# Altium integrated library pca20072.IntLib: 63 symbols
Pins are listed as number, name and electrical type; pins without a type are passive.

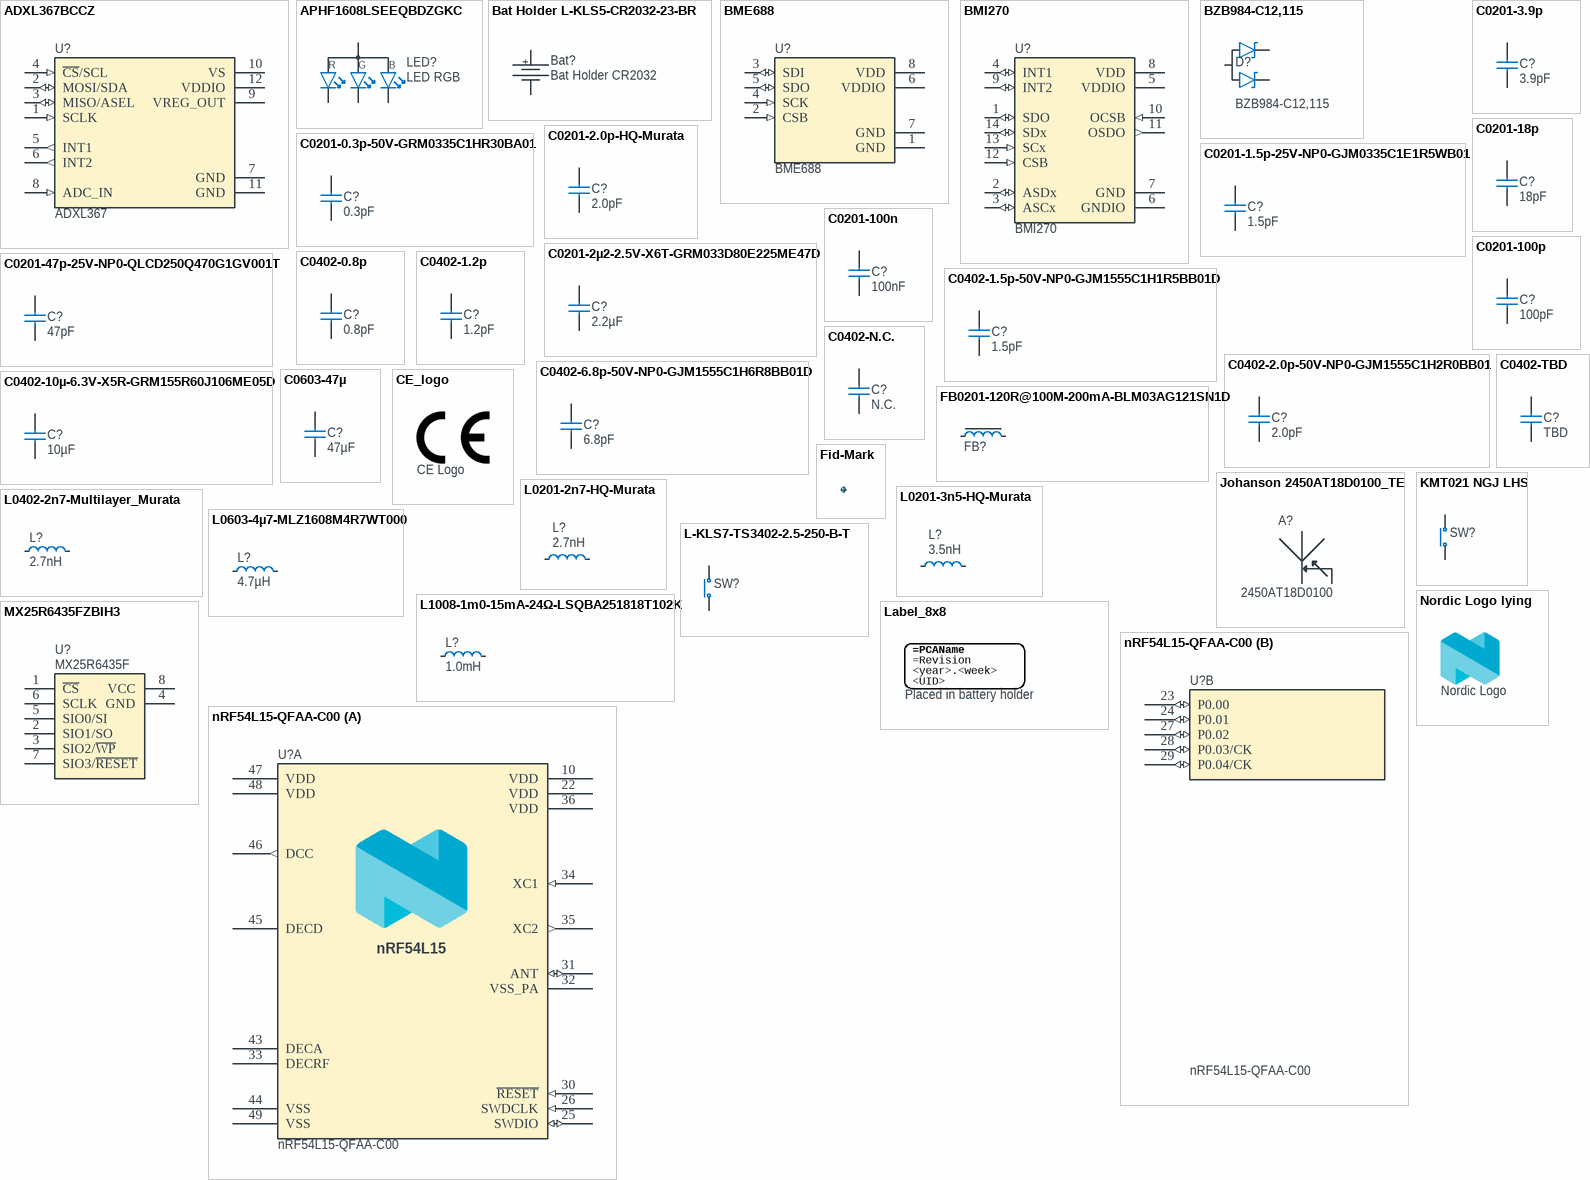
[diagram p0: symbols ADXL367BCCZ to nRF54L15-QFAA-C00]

## ADXL367BCCZ
designator U?, comment ADXL367
Micropower, 3-Axis, ±2 g/±4 g/±8 g Digital Output MEMS Accelerometer; Part Number: ADXL367BCCZ; Manufacturer: Analog Devices; Part number NEMS: 101900775; Note: N.A.; Component Status: Active; Pad Count: 12
footprint LGA50P220X230X97-12N
pins: 1 SCLK (in), 2 MOSI/SDA (io), 3 MISO/ASEL (io), 4 ~{CS}/SCL (in), 5 INT1 (out), 6 INT2 (out), 7 GND (power), 8 ADC_IN (in), 9 VREG_OUT (power), 10 VS (power), 11 GND (power), 12 VDDIO (power)

## APHF1608LSEEQBDZGKC
designator LED?, comment LED RGB
RGB LED 1.60 mm x 0.80 mm SMD; Part Number: APHF1608LSEEQBDZGKC; Manufacturer: Kingbright Company LLC; Part number IPS: 00000001254; Part number Norautron: 26470023; Part number NEMS: 101400123; Note: N.A.; Pad Count: 4; Component Status: Active
footprint LED_RGB_0603
pins: 1 C_RED, 2 C_GREEN, 3 C_BLUE, 4 A

## Bat Holder L-KLS5-CR2032-23-BR
designator Bat?, comment Bat Holder CR2032
Bat Holder CR2032 SMD; Part Number: Bat Holder L-KLS5-CR2032-23-BR; Manufacturer: KLS Electronic; Manufacturer Part Number: L-KLS5-CR2032-23-BR; Part number NEMS: 100500651; Component Status: Active; Pad Count: 2; Artikkelnr Noca: N.A.; System: Connector
footprint L-KLS5-CR2032-23-B1
pins: 1, 2

## BME688
designator U?
Low power gas, pressure, temperature & humidity sensor; Manufacturer: Bosch; Part number NEMS: 101900619; Component Status: Active; Pad Count: 8; Note: N.A.
footprint BME680
pins: 1 GND (power), 2 CSB (in), 3 SDI (io), 4 SCK (in), 5 SDO (io), 6 VDDIO (power) "1.2V - 3.6V", 7 GND (power), 8 VDD (power) "1.71V - 3.6V"

## BMI270
designator U?
6-axis, smart, low-power, inertial measurement unit; Manufacturer: Bosch; Part number NEMS: 101900620; Note: N.A.; Pad Count: 14; Component Status: Active
footprint BMI270
pins: 1 SDO (io), 2 ASDx (io), 3 ASCx (io), 4 INT1 (io), 5 VDDIO (power), 6 GNDIO (power), 7 GND (power), 8 VDD (power), 9 INT2 (io), 10 OCSB (in), 11 OSDO (out), 12 CSB (in), 13 SCx (in), 14 SDx (io)

## BZB984-C12,115
designator D?
Zener Diode Array, 1 Pair, Common Anode, 12V, 265mW, ±5%; Manufacturer: Nexperia; Part number NEMS: 101300214; Component Status: Active; Pad Count: 3; Note: N.A.
footprint SOTFL50P160X60-3L
pins: 1 K1, 2 K2, 3 CA
1 alternate drawing of the same symbol

## C0201-0.3p-50V-GRM0335C1HR30BA01
designator C?, comment 0.3pF
Capacitor, C0G, ±0.1pF, 50V; Part Number: C0201-0.3p-50V-GRM0335C1HR30BA01; Manufacturer: Murata; Manufacturer Part Number: GRM0335C1HR30BA01; Part number NEMS: 100200650; Component Status: Active; Pad Count: 2; Artikkelnr Noca: N.A.
footprint CAPC0603X03L_C
pins: 1, 2

## C0201-1.5p-25V-NP0-GJM0335C1E1R5WB01
designator C?, comment 1.5pF
Capacitor, NP0, ±0.05pF, 25V, High Q; Part Number: C0201-1.5p-25V-NP0-GJM0335C1E1R5WB01; Manufacturer: Murata; Manufacturer Part Number: GJM0335C1E1R5WB01; Part number NEMS: 100200477; Component Status: Active; Pad Count: 2; Artikkelnr Noca: N.A.
footprint CAPC0603X03L_C
pins: 1, 2

## C0201-2.0p-HQ-Murata
designator C?, comment 2.0pF
Capacitor, NP0, ±0.05pF, 25V; Part Number: C0201-2.0p-HQ-Murata; Manufacturer: Murata; Manufacturer Part Number: GJM0335C1E2R0WB01; Part number IPS: 00000001775; Part number NEMS: 100200419; Component Status: Active; Pad Count: 2; Artikkelnr Noca: N.A.
footprint CAPC0603X03L_C
pins: 1, 2

## C0201-2µ2-2.5V-X6T-GRM033D80E225ME47D
designator C?, comment 2.2µF
Capacitor, Ceramic, 2.2µF 2.5V X6T 0201,±20%; Part Number: C0201-2µ2-2.5V-X6T-GRM033D80E225ME47D; Manufacturer: Murata; Manufacturer Part Number: GRM033D80E225ME47D; Part number NEMS: 100200527; Component Status: Active; Pad Count: 2; Note: 2.5V, 20%, X6T; Artikkelnr Noca: N.A.
footprint CAPC0603X03L_C
pins: 1, 2

## C0201-3.9p
designator C?, comment 3.9pF
Chip Cap 0201; Part Number: C0201-3.9p; Manufacturer: N.A.; Part number NEMS: 100200024,100200424; Component Status: Active; Pad Count: 2; Note: Chip Cap 1%
footprint CAPC0603X03L_C
pins: 1, 2

## C0201-18p
designator C?, comment 18pF
Capacitor, C0G, ±5%, 25V; Part Number: C0201-18p; Manufacturer: Walsin Technology Corporation; Manufacturer Part Number: 0201N180J250CT; Part number IPS: 00000000862; Part number Norautron: 26207023; Part number NEMS: 100200035; Component Status: Active; Pad Count: 2; Note: Chip Cap 5%; Artikkelnr Noca: N.A.
footprint CAPC0603X03L_C
pins: 1, 2

## C0201-47p-25V-NP0-QLCD250Q470G1GV001T
designator C?, comment 47pF
Capacitor, High Q, Low Loss, C0G/NP0, 25V, ±2%, -55°C ~ 125°C; Part Number: C0201-47p-25V-NP0-QLCD250Q470G1GV001T; Manufacturer: Johanson Technology; Manufacturer Part Number: QLCD250Q470G1GV001T; Part number IPS: 00000010810; Component Status: Active; Pad Count: 2; Artikkelnr Noca: N.A.
footprint CAPC0603X03L_C
pins: 1, 2

## C0201-100n
designator C?, comment 100nF
Capacitor, X5R, ±10%, 100nF, 16V; Part Number: C0201-100n; Manufacturer: N.A.; Part number IPS: 00000001248, 00000002505; Part number Norautron: 262071862; Part number NEMS: 100200078; Pad Count: 2; Component Status: Active
footprint CAPC0603X03L_C
pins: 1, 2

## C0201-100p
designator C?, comment 100pF
Capacitor, NP0, ±2%, 25V; Part Number: C0201-100p; Manufacturer: Murata; Manufacturer Part Number: GRM0335C1E101GA01D; Part number IPS: 00000007853; Part number NEMS: 100200044; Component Status: Active; Pad Count: 2; Artikkelnr Noca: N.A.
footprint CAPC0603X03L_C
pins: 1, 2

## C0402-0.8p
designator C?, comment 0.8pF
Capacitor, NP0, ±5%; Part Number: C0402-0.8p; Manufacturer: Murata; Manufacturer Part Number: GRM1555C1HR80WA01D; Part number IPS: 00000007782; Part number Norautron: N.A.; Part number NEMS: 100200116; Component Status: Active; Pad Count: 2; Note: 50V; Artikkelnr Noca: 20029147
footprint CAPC1005X04L
footprint CAPC1005X04L_C2
pins: 1, 2

## C0402-1.2p
designator C?, comment 1.2pF
Capacitor, NP0, ±0.1pF; Part Number: C0402-1.2p; Manufacturer: N.A.; Part number IPS: 00000005410; Part number NEMS: 100200119; Component Status: Active; Pad Count: 2; Note: 50V; Artikkelnr Noca: 20029157
footprint CAPC1005X04L
footprint CAPC1005X04L_C2
pins: 1, 2

## C0402-1.5p-50V-NP0-GJM1555C1H1R5BB01D
designator C?, comment 1.5pF
Capacitor, High Q, Low Loss, C0G/NP0, 50V, ±0.1pF, -55°C ~ 125°C; Part Number: C0402-1.5p-50V-NP0-GJM1555C1H1R5BB01D; Manufacturer: Murata; Manufacturer Part Number: GJM1555C1H1R5BB01D; Part number IPS: 80000004967; Component Status: Active; Pad Count: 2; Artikkelnr Noca: N.A.
footprint CAPC1005X04L
footprint CAPC1005X04L_C2
pins: 1, 2

## C0402-2.0p-50V-NP0-GJM1555C1H2R0BB01
designator C?, comment 2.0pF
Capacitor, High Q, Low Loss, C0G/NP0, 50V, ±0.1pF, -55°C ~ 125°C; Part Number: C0402-2.0p-50V-NP0-GJM1555C1H2R0BB01; Manufacturer: Murata; Manufacturer Part Number: GJM1555C1H2R0BB01; Part number IPS: 80000004957; Part number NEMS: 100200697; Component Status: Active; Pad Count: 2; Artikkelnr Noca: N.A.
footprint CAPC1005X04L
footprint CAPC1005X04L_C2
pins: 1, 2

## C0402-6.8p-50V-NP0-GJM1555C1H6R8BB01D
designator C?, comment 6.8pF
Capacitor, High Q, Low Loss, C0G/NP0, 50V, ±0.1pF, -55°C ~ 125°C; Part Number: C0402-6.8p-50V-NP0-GJM1555C1H6R8BB01D; Manufacturer: Murata; Manufacturer Part Number: GJM1555C1H6R8BB01D; Part number IPS: 80000004966; Component Status: Active; Pad Count: 2; Artikkelnr Noca: N.A.
footprint CAPC1005X04L
footprint CAPC1005X04L_C2
pins: 1, 2

## C0402-10µ-6.3V-X5R-GRM155R60J106ME05D
designator C?, comment 10µF
Capacitor, X5R, ±20%, 6.3V; Part Number: C0402-10µ-6.3V-X5R-GRM155R60J106ME05D; Manufacturer: Murata; Manufacturer Part Number: GRM155R60J106ME05D; Part number NEMS: 100200554; Component Status: Active; Pad Count: 2; Artikkelnr Noca: N.A.
footprint CAPC1005X04L_C2
pins: 1, 2

## C0402-N.C.
designator C?, comment N.C.
Not mounted; Part Number: C0402-N.C.; Manufacturer: N.A.; Part number NEMS: 100200105; Component Status: Active; Pad Count: 2; Note: Chip Cap; Assembly: Not mounted
footprint CAPC1005X04L_C2
pins: 1, 2

## C0402-TBD
designator C?, comment TBD
Chip Cap 0402; Part Number: C0402-TBD; Manufacturer: N.A.; Part number NEMS: 100200106; Pad Count: 2; Component Status: Active
footprint CAPC1005X04L
footprint CAPC1005X04L_C2
pins: 1, 2

## C0603-47µ
designator C?, comment 47µF
Capacitor, X5R, ±20%, 6.3V; Part Number: C0603-47µ; Manufacturer: N.A.; Part number IPS: 00000001818; Part number NEMS: 100200277; Component Status: Active; Pad Count: 2
footprint CAPC1608X06L
pins: 1, 2

## CE_logo
designator LOGO?, comment CE Logo  (no BOM)
CE (Conformité_Européenne) logo; Part Number: CE_logo; Manufacturer: N.A.; Part number NEMS: 101100010; Component Status: Active; Pad Count: 0
footprint CE_logo

## FB0201-120R@100M-200mA-BLM03AG121SN1D
designator FB?, comment 120R/0.2A  (value not drawn)
Ferrite Bead, 120 Ohm @ 100MHz, 200mA, 500 mOhm Max; Part Number: FB0201-120R@100M-200mA-BLM03AG121SN1D; Manufacturer: Murata; Manufacturer Part Number: BLM03AG121SN1D; Part number NEMS: 100300419; Component Status: Active; Pad Count: 2; Artikkelnr Noca: N.A.
footprint INDC0603X03L_C
pins: 1, 2

## Fid-Mark
designator Fid?, comment Fiducial mark  (value not drawn)
Part Number: Fid-Mark; Manufacturer: N.A.; Part number NEMS: 100500073; Value: N.A.; Pad Count: 1; Component Status: Active; System: Connector
footprint Fiducial

## Johanson 2450AT18D0100_TE
designator A?, comment 2450AT18D0100
2.45 GHz chip antenna; Part Number: Johanson 2450AT18D0100_TE; Manufacturer: Johanson Technology; Part number IPS: 00000001415; Part number NEMS: 100700004, 100700005, 100700006; Component Status: Active; Pad Count: 4; Note: N.A.; Artikkelnr Noca: 53059035
footprint 2450AT18D0100_TE-L
footprint 2450AT18D0100_TE-R
pins: 1, 2 GND (power) hidden to GND, 3 Tuning

## KMT021 NGJ LHS
designator SW?, comment PB SW  (value not drawn)
Nano-Miniature Top Actuated Tact Switch with extended life 3.0x2.6mm; Part Number: KMT021 NGJ LHS; Manufacturer: C&K; Part number IPS: 00000005416; Part number NEMS: 101500039; Note: N.A.; Pad Count: 4; Component Status: Active
footprint SW_TACTILE_2.6x3.0MM_4-LEAD
pins: 1 N.O, 2 COM

## L0201-2n7-HQ-Murata
designator L?, comment 2.7nH
Inductor, 600mA, ±0.1ｎH, 120mOhm; Part Number: L0201-2n7-HQ-Murata; Manufacturer: Murata; Manufacturer Part Number: LQP03HQ2N7B02; Part number IPS: 00000001753; Part number NEMS: 100300214; Component Status: Active; Pad Count: 2; Note: -55°C ~ 125°C; Artikkelnr Noca: N.A.
footprint INDC0603X03L_C
pins: 1, 2

## L0201-3n5-HQ-Murata
designator L?, comment 3.5nH
Inductor, 500mA, ±0.1ｎH, 170mOhm; Part Number: L0201-3n5-HQ-Murata; Manufacturer: Murata; Manufacturer Part Number: LQP03HQ3N5B02; Part number NEMS: 100300222; Component Status: Active; Pad Count: 2; Note: -55°C ~ 125°C; Artikkelnr Noca: N.A.
footprint INDC0603X03L_C
pins: 1, 2

## L0402-2n7-Multilayer_Murata
designator L?, comment 2.7nH
Inductor, 800mA, ±2%, 120mΩ; Part Number: L0402-2n7-Multilayer_Murata; Manufacturer: Murata; Manufacturer Part Number: LQG15HS2N7B02D; Part number NEMS: 100300445; Component Status: Active; Pad Count: 2; Note: -55°C ~ 125°C; Artikkelnr Noca: N.A.
footprint INDC1005X04L_C2 (Chip Inductor, 2-Leads, Body 1.0x0.5mm, IPC High Density)
pins: 1, 2

## L0603-4µ7-MLZ1608M4R7WT000
designator L?, comment 4.7µH
Inductor, 120mA, ±20%, 0.65R; Part Number: L0603-4µ7-MLZ1608M4R7WT000; Manufacturer: TDK Corporation; Manufacturer Part Number: MLZ1608M4R7WT000; Part number NEMS: 100300440; Component Status: Active; Pad Count: 2; Note: Power Inductor ±20%; Artikkelnr Noca: N.A.
footprint INDC1608X06L
pins: 1, 2

## L1008-1m0-15mA-24Ω-LSQBA251818T102K
designator L?, comment 1.0mH
Inductor, 15mA, ±10%, 24Ω; Part Number: L1008-1m0-15mA-24Ω-LSQBA251818T102K; Manufacturer: Taiyo Yuden; Manufacturer Part Number: LSQBA251818T102K; Part number NEMS: 100300509; Component Status: Active; Pad Count: 2; Note: -40°C ~ 105°C; Artikkelnr Noca: N.A.
footprint INDC2520X10N
pins: 1, 2

## L-KLS7-TS3402-2.5-250-B-T
designator SW?, comment PB SW  (value not drawn)
Tactile Switch, SPNO, SMD, 260gf, 4.2x3.3x2.5mm; Part Number: L-KLS7-TS3402-2.5-250-B-T; Manufacturer: KLS Electronic; Part number NEMS: 101500152; Note: N.A.; Pad Count: 4; Component Status: Active
footprint KLS-TS3402
pins: 1 N.O, 2 COM

## Label_8x8
designator LABEL?, comment Assembly: Placed in battery holder  (hidden comment: 8x8mm)
PCA version label, stick-on, 8x8mm; Part Number: Label_8x8; Manufacturer: Ellco Etikett; Manufacturer Part Number: A33511-01; Part number NEMS: 101200025; Component Status: Active; Pad Count: 0; Note: N.A.
footprint LabelSilk_8x8

## MX25R6435FZBIH3
designator U?, comment MX25R6435F
Ultra low power, 64M-bit, serial multi I/O flash memory; Part Number: MX25R6435FZBIH3; Manufacturer: Macronix; Part number NEMS: 101900860; Note: N.A.; Pad Count: 8; Component Status: Active
footprint SON80P300X60_HS-9N
pins: 1 ~{CS}, 2 SIO1/SO, 3 SIO2/~{WP}, 4 GND, 5 SIO0/SI, 6 SCLK, 7 SIO3/~{RESET}, 8 VCC, 9 GND hidden to GND

## Nordic Logo lying
designator LOGO?, comment Nordic Logo  (no BOM)
Nordic logo lying; Manufacturer: N.A.; Part number NEMS: 101100001; Component Status: Active; Pad Count: 0
footprint NORDIC_LOGO_LYING

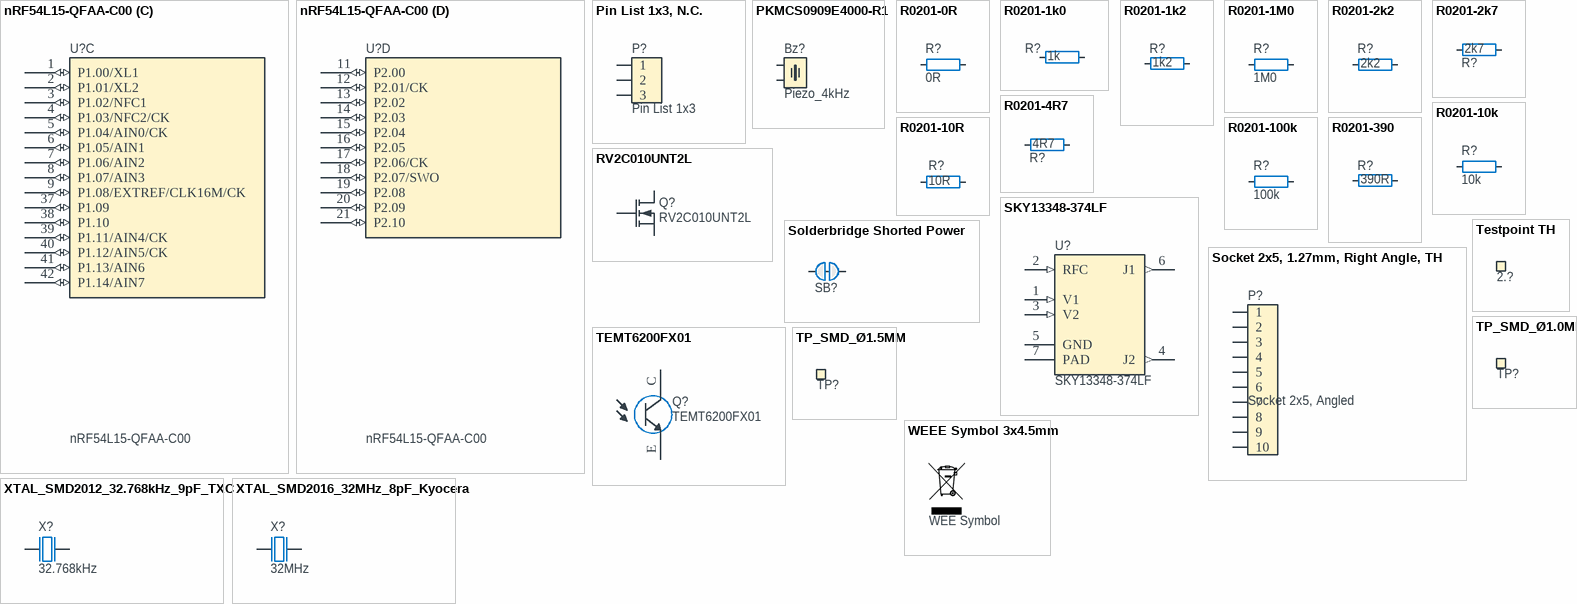
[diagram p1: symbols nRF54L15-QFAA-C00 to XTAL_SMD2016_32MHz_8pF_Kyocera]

## nRF54L15-QFAA-C00
designator U?
Multi-protocol Bluetooth Low Energy, IEEE 802.15.4 and 2.4GHz proprietary Wireless MCU; Manufacturer: Nordic Semiconductor; Part number NEMS: 102000382; Component Status: Active; Pad Count: 49; Note: N.A.
footprint QFN49P40_600x600x90L40x20T460N
footprint QFN49P40_600x600x90L40x20T460L
footprint QFN40P600X600X90-48N
part A pins: 10 VDD (power), 22 VDD (power), 25 SWDIO (io), 26 SWDCLK (in), 30 ~{RESET} (in), 31 ANT (io), 32 VSS_PA (power), 33 DECRF (power), 34 XC1 (in), 35 XC2 (out), 36 VDD (power), 43 DECA (power), 44 VSS (power), 45 DECD (power), 46 DCC (out), 47 VDD (power), 48 VDD (power), 49 VSS (power)
part B pins: 23 P0.00 (io), 24 P0.01 (io), 27 P0.02 (io), 28 P0.03/CK (io), 29 P0.04/CK (io)
part C pins: 1 P1.00/XL1 (io), 2 P1.01/XL2 (io), 3 P1.02/NFC1 (io), 4 P1.03/NFC2/CK (io), 5 P1.04/AIN0/CK (io), 6 P1.05/AIN1 (io), 7 P1.06/AIN2 (io), 8 P1.07/AIN3 (io), 9 P1.08/EXTREF/CLK16M/CK (io), 37 P1.09 (io), 38 P1.10 (io), 39 P1.11/AIN4/CK (io), 40 P1.12/AIN5/CK (io), 41 P1.13/AIN6 (io), 42 P1.14/AIN7 (io)
part D pins: 11 P2.00 (io), 12 P2.01/CK (io), 13 P2.02 (io), 14 P2.03 (io), 15 P2.04 (io), 16 P2.05 (io), 17 P2.06/CK (io), 18 P2.07/SWO (io), 19 P2.08 (io), 20 P2.09 (io), 21 P2.10 (io)

## Pin List 1x3, N.C.
designator P?, comment Pin List 1x3
Pin List 1x3, 2.54mm (100mil); Part Number: Pin List 1x3, N.C.; Manufacturer: N.A.; Part number NEMS: 100500305; Component Status: Active; Pad Count: 3; Assembly: Not mounted; System: Connector
footprint LIST_1x3-NC
pins: 1, 2, 3

## PKMCS0909E4000-R1
designator Bz?, comment Piezo_4kHz
Piezo Buzzer, SMD, 9.0mm x 9.0mm x 1.9mm, 4kHz, 65dB @ 1.5V, <12.5Vp-p; Part Number: PKMCS0909E4000-R1; Manufacturer: Murata; Part number NEMS: 101000026; Component Status: Active; Pad Count: 2; Note: 1.5 ~ 12.5V; Artikkelnr Noca: N.A.
footprint Buzzer_PKMCS0909
pins: 1, 2

## R0201-0R
designator R?, comment 0R
Resistor, ±5%, 0.05W; Part Number: R0201-0R; Manufacturer: N.A.; Part number IPS: 00000003245; Part number NEMS: 100100001; Note: Chip Res 5%; Pad Count: 2; Component Status: Active
footprint RESC0603X03L_C
pins: 1, 2

## R0201-1k0
designator R?, comment 1k
Resistor, ±1%, 0.05W; Part Number: R0201-1k0; Manufacturer: N.A.; Part number IPS: 00000005786; Part number NEMS: 100100043; Component Status: Active; Pad Count: 2; Note: Chip Res 1%
footprint RESC0603X03L_C
pins: 1, 2

## R0201-1k2
designator R?, comment 1k2
Resistor, ±1%, 0.05W; Part Number: R0201-1k2; Manufacturer: N.A.; Part number IPS: 00000001256; Part number Norautron: 26107084; Part number NEMS: 100100045; Note: Chip Res 1%; Pad Count: 2; Component Status: Active
footprint RESC0603X03L_C
pins: 1, 2

## R0201-1M0
designator R?, comment 1M0
Resistor, ±1%, 0.05W; Part Number: R0201-1M0; Manufacturer: N.A.; Part number IPS: 00000001418; Part number Norautron: 26107108; Part number NEMS: 100100093; Component Status: Active; Pad Count: 2; Note: Chip Res 1%
footprint RESC0603X03L_C
pins: 1, 2

## R0201-2k2
designator R?, comment 2k2
Resistor, ±1%, 0.05W; Part Number: R0201-2k2; Manufacturer: N.A.; Part number IPS: 00000001257; Part number Norautron: 26470030; Part number NEMS: 100100052; Note: Chip Res 1%; Pad Count: 2; Component Status: Active
footprint RESC0603X03L_C
pins: 1, 2

## R0201-2k7
designator R?, comment 2k7
Resistor, ±1%, 0.05W; Part Number: R0201-2k7; Manufacturer: N.A.; Part number Norautron: 26108481; Part number NEMS: 100100054; Component Status: Active; Pad Count: 2; Note: Chip Res 1%
footprint RESC0603X03L_C
pins: 1, 2

## R0201-4R7
designator R?, comment 4R7
Resistor, ±1%, 0.05W; Part Number: R0201-4R7; Manufacturer: N.A.; Part number IPS: 00000002486; Part number NEMS: 100100010; Component Status: Active; Pad Count: 2; Note: Chip Res 1%
footprint RESC0603X03L_C
pins: 1, 2

## R0201-10k
designator R?, comment 10k
Resistor, ±1%, 0.05W; Part Number: R0201-10k; Manufacturer: N.A.; Part number IPS: 00000001255; Part number Norautron: 26107101; Part number NEMS: 100100065; Component Status: Active; Pad Count: 2; Note: Chip Res 1%
footprint RESC0603X03L_C
pins: 1, 2

## R0201-10R
designator R?, comment 10R
Resistor, ±1%, 0.05W; Part Number: R0201-10R; Manufacturer: N.A.; Part number NEMS: 100100014; Component Status: Active; Pad Count: 2; Note: Chip Res 1%
footprint RESC0603X03L_C
pins: 1, 2

## R0201-100k
designator R?, comment 100k
Resistor, ±1%, 0.05W; Part Number: R0201-100k; Manufacturer: N.A.; Part number IPS: 00000001419; Part number Norautron: 26108487; Part number NEMS: 100100080; Note: Chip Res 1%; Pad Count: 2; Component Status: Active
footprint RESC0603X03L_C
pins: 1, 2

## R0201-390
designator R?, comment 390R
Resistor, ±1%, 0.05W; Part Number: R0201-390; Manufacturer: N.A.; Part number IPS: 00000001258; Part number Norautron: 26470031; Part number NEMS: 100100035; Note: Chip Res 1%; Pad Count: 2; Component Status: Active
footprint RESC0603X03L_C
pins: 1, 2

## RV2C010UNT2L
designator Q?
N-Channel MOSFET, 20V, 1A, 470mOhm, 400mW, -55°C ~ 150°C; Manufacturer: Rohm Semiconductor; Part number IPS: 00000009976; Part number Norautron: 26320026; Part number NEMS: 101300132; Component Status: Active; Pad Count: 3; Note: N.A.; Artikkelnr Noca: 35010020
footprint DFN65P100X40-3L
pins: 1 G, 2 S, 3 D

## SKY13348-374LF
designator U?
50 MHz-6.0 GHz GaAs SPDT Switch; Manufacturer: Skyworks; Part number NEMS: 101900872; Component Status: Active; Pad Count: 6; Note: N.A.
footprint SON50P150X50_HS-7N
pins: 1 V1 (in), 2 RFC (in), 3 V2 (in), 4 J2 (out), 5 GND (power), 6 J1 (out), 7 PAD (power)

## Socket 2x5, 1.27mm, Right Angle, TH
designator P?, comment Socket 2x5, Angled
Socket 2x5, 1.27mm (50mil), Right Angle, TH; Part Number: Socket 2x5, 1.27mm, Right Angle, TH; Manufacturer: WCON; Manufacturer Part Number: 2344-205RS0CUNR3; Part number NEMS: 100500894; Note: (Replaced 2344-205RS0CUNR1); Artikkelnr Noca: N.A.; Pad Count: 10; Component Status: Active; System: Connector
footprint SOCKET_ANG_2x5_TH-1.27mm
pins: 1, 2, 3, 4, 5, 6, 7, 8, 9, 10
1 alternate drawing of the same symbol

## Solderbridge Shorted Power
designator SB?, comment Solderbridge  (value not drawn)  (net tie, no BOM)
Shorted Solderbridge Power; Part Number: Solderbridge Shorted Power; Manufacturer: N.A.; Part number NEMS: 100500460; Pad Count: 2; Component Status: Active; System: Connector
footprint Solderbridge_Shorted_Power
pins: 1 0, 2 1

## TEMT6200FX01
designator Q?
Phototransistors 550nm Top View 0805 (2012 Metric); Manufacturer: Vishay; Part number NEMS: 101400145; Component Status: Active; Pad Count: 2; Note: N.A.
footprint TEMT6200FX01
pins: C, E

## Testpoint TH
designator 2.?, comment TP  (value not drawn)  (no BOM)
Testpoint, through hole; Part Number: Testpoint TH; Manufacturer: N.A.; Part number NEMS: 100500464; Component Status: Active; Pad Count: 1
footprint TESTPAD-TH
pins: 1

## TP_SMD_Ø1.0MM
designator TP?, comment Ø1.0mm,SMD  (value not drawn)  (no BOM)
1.0mm circular SMD testpad; Part Number: TP_SMD_Ø1.0MM; Manufacturer: Nordic Semiconductor; Manufacturer Part Number: N.A.; Part number NEMS: 100500475; Component Status: Active; Pad Count: 1
footprint TP_SMD_D1.0mm
pins: 1

## TP_SMD_Ø1.5MM
designator TP?, comment Ø1.5mm,SMD  (value not drawn)  (no BOM)
1.5mm circular SMD testpad; Part Number: TP_SMD_Ø1.5MM; Manufacturer: Nordic Semiconductor; Manufacturer Part Number: N.A.; Part number NEMS: 100500477; Component Status: Active; Pad Count: 1
footprint TP_SMD_D1.5mm
pins: 1

## WEEE Symbol 3x4.5mm
designator LOGO?, comment WEE Symbol  (no BOM)
WEEE Directive symbol; Part Number: WEEE Symbol 3x4.5mm; Manufacturer: N.A.; Part number NEMS: 101100006; Component Status: Active; Pad Count: 0
footprint WEEE_3x4.5mm

## XTAL_SMD2012_32.768kHz_9pF_TXC
designator X?, comment 32.768kHz
XTAL SMD 2012, 32.768kHz, 9pF, ±20ppm; Part Number: XTAL_SMD2012_32.768kHz_9pF_TXC; Manufacturer: TXC Corporation; Manufacturer Part Number: 9HT11-32.768KDZC-T; Part number NEMS: 101600107; Component Status: Active; Pad Count: 2; Note: XTAL SMD 32.768kHz; Artikkelnr Noca: N.A.
footprint XTAL_2012
pins: 1 inp, 2 out

## XTAL_SMD2016_32MHz_8pF_Kyocera
designator X?, comment 32MHz
XTAL SMD 2016, 32MHz, Cl=8pF, Tot: ±40ppm; Part Number: XTAL_SMD2016_32MHz_8pF_Kyocera; Manufacturer: Kyocera; Manufacturer Part Number: CX2016DB32000D0WZRC1; Part number IPS: 00000007827; Part number Norautron: 26511136; Part number NEMS: 101600039; Component Status: Active; Pad Count: 4; Note: XTAL SMD 32.000MHz; Artikkelnr Noca: 22010022
footprint BT-XTAL_2016
pins: 1 inp, 2 GND hidden to GND, 3 out, 4 GND hidden to GND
